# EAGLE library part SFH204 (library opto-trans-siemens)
Quad PHOTO DIODE
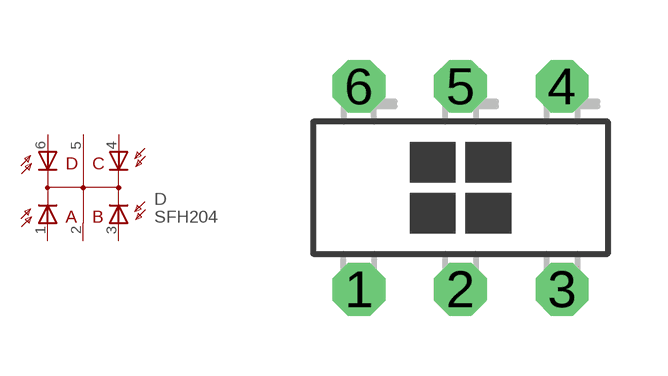
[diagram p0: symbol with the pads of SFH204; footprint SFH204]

Designator prefix D

## SFH204 (OC_FARNELL: unknown; OC_NEWARK: unknown)  [SFH204]
1  1  pas
2  2  pas
3  3  pas
4  4  pas
5  5  pas
6  6  pas

## Footprint SFH204 (pad centres in mm)
Quad PHOTO DIODE
drill 0.813 octagon: 1 -2.54,-2.54; 2 0,-2.54; 3 2.54,-2.54; 4 2.54,2.54; 5 0,2.54; 6 -2.54,2.54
